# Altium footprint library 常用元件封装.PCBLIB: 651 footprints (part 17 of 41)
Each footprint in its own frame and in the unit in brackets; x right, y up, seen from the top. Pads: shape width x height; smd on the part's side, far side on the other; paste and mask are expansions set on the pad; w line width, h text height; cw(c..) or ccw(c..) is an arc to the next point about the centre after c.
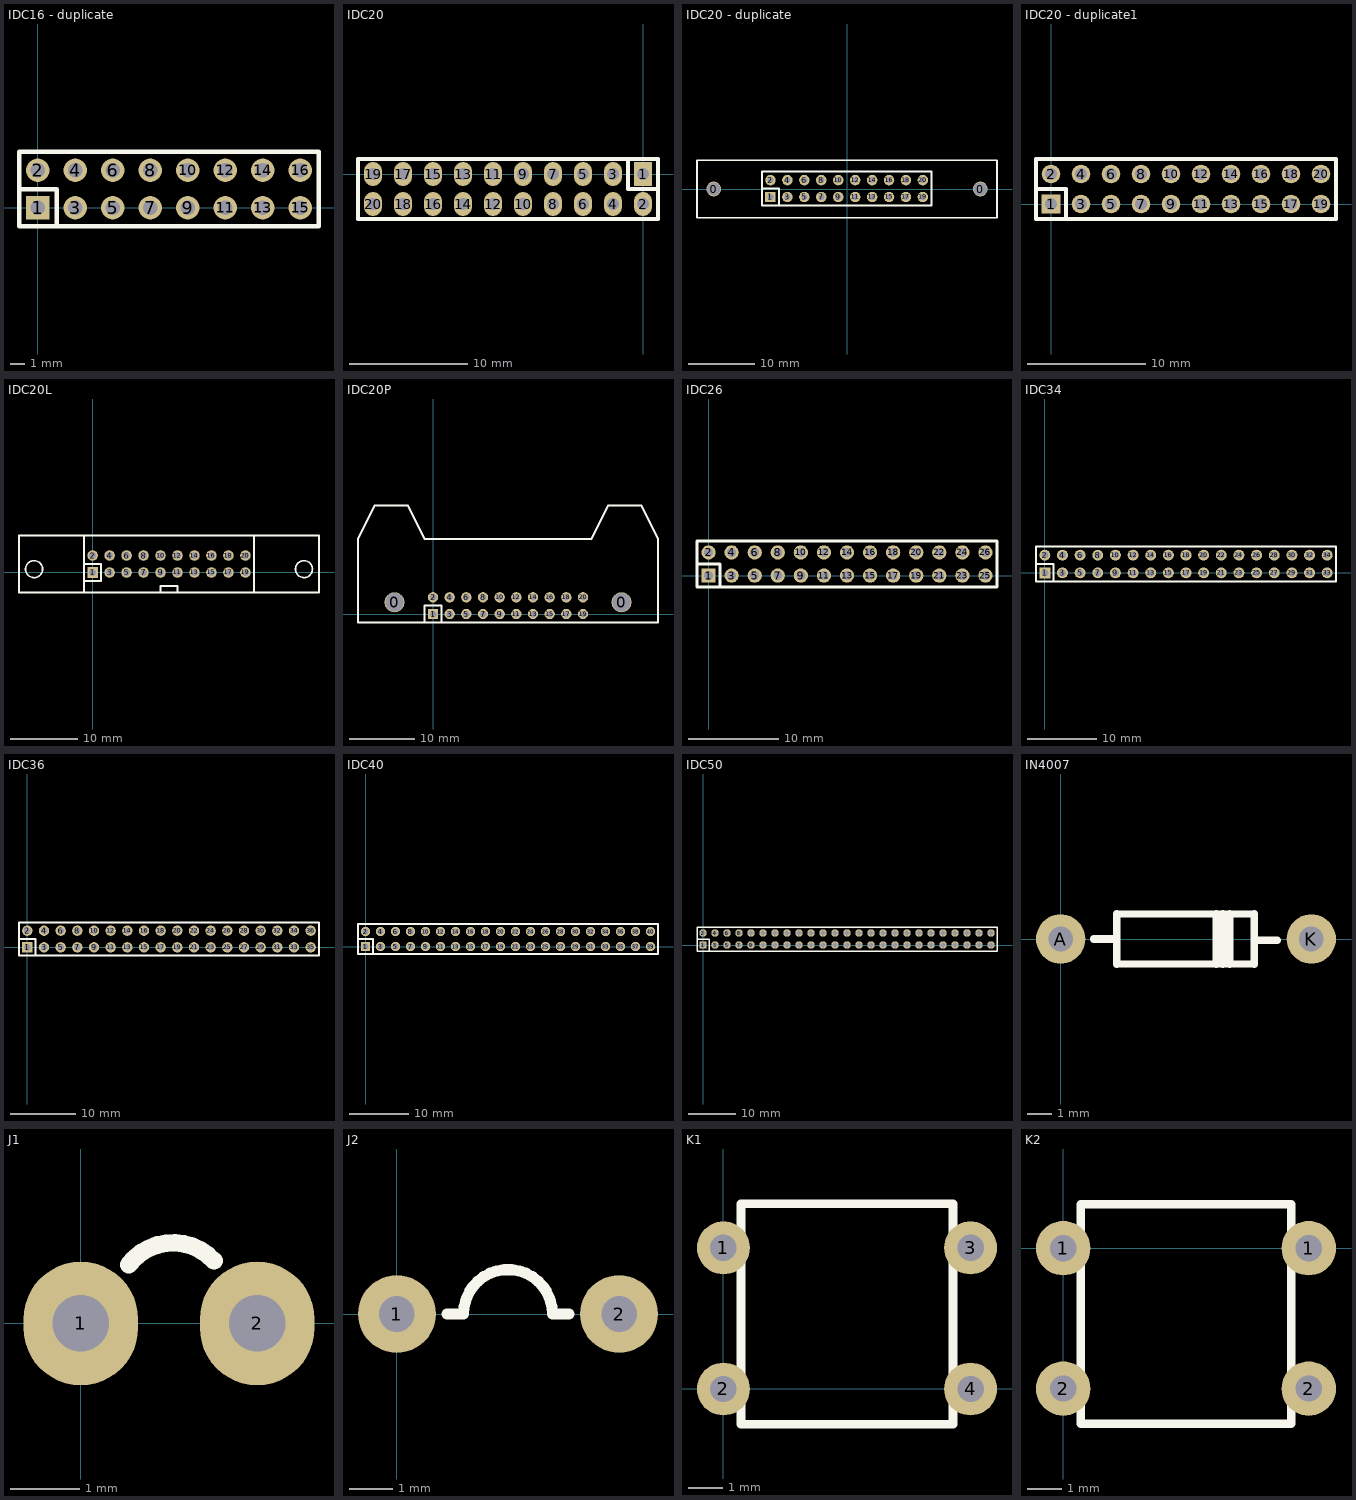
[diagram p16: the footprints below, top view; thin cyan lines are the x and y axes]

## IDC16 - duplicate [mil]
pads (16):
  rect 62x62 hole 39: 1(0,0)
  round 62 hole 39: 2(0,100) 3(100,0) 4(100,100) 5(200,0) 6(200,100) 7(300,0) 8(300,100) 9(400,0) 10(400,100) 11(500,0) 12(500,100) 13(600,0) 14(600,100) 15(700,0) 16(700,100)
TopOverlay:
  lines w12: -50,50 50,50 50,-50 ; -50,-50 750,-50 750,150 -50,150 -50,-50

## IDC20 [mil]
pads (20):
  rect 60x80 hole 40: 1(0,0)
  oval 60x80 hole 40: 2(0,-100) 3(-100,0) 4(-100,-100) 5(-200,0) 6(-200,-100) 7(-300,0) 8(-300,-100) 9(-400,0) 10(-400,-100) 11(-500,0) 12(-500,-100) 13(-600,0) 14(-600,-100) 15(-700,0) 16(-700,-100) 17(-800,0) 18(-800,-100) 19(-900,0) 20(-900,-100)
TopOverlay:
  lines w12: -50,50 -50,-50 50,-50 ; -950,-150 -950,50 50,50 50,-150 -950,-150

## IDC20 - duplicate [mm]
pads (22):
  round 2.2 hole 2: 0(-20,0) 0(20,0)
  rect 1.575x1.575 hole 0.9: 1(-11.476,-1.2)
  round 1.575 hole 0.9: 2(-11.476,1.34) 3(-8.936,-1.2) 4(-8.936,1.34) 5(-6.396,-1.2) 6(-6.396,1.34) 7(-3.856,-1.2) 8(-3.856,1.34) 9(-1.316,-1.2) 10(-1.316,1.34) 11(1.224,-1.2) 12(1.224,1.34) 13(3.764,-1.2) 14(3.764,1.34) 15(6.304,-1.2) 16(6.304,1.34) 17(8.844,-1.2) 18(8.844,1.34) 19(11.384,-1.2) 20(11.384,1.34)
TopOverlay:
  lines w0.254: -22.5,-4.3 -22.5,4.3 22.5,4.3 22.5,-4.3 -22.5,-4.3
  lines w0.305: -12.746,0.07 -10.206,0.07 -10.206,-2.47 ; -12.746,-2.47 12.654,-2.47 12.654,2.61 -12.746,2.61 -12.746,-2.47

## IDC20 - duplicate1 [mil]
pads (20):
  rect 62x62 hole 39: 1(0,0)
  round 62 hole 39: 2(0,100) 3(100,0) 4(100,100) 5(200,0) 6(200,100) 7(300,0) 8(300,100) 9(400,0) 10(400,100) 11(500,0) 12(500,100) 13(600,0) 14(600,100) 15(700,0) 16(700,100) 17(800,0) 18(800,100) 19(900,0) 20(900,100)
TopOverlay:
  lines w12: -50,50 50,50 50,-50 ; -50,-50 950,-50 950,150 -50,150 -50,-50

## IDC20L [mil]
pads (20):
  rect 62x62 hole 39: 1(0,0)
  round 62 hole 39: 2(0,100) 3(100,0) 4(100,100) 5(200,0) 6(200,100) 7(300,0) 8(300,100) 9(400,0) 10(400,100) 11(500,0) 12(500,100) 13(600,0) 14(600,100) 15(700,0) 16(700,100) 17(800,0) 18(800,100) 19(900,0) 20(900,100)
TopOverlay:
  circle w10: c1244.49,19.68 r50
  circle w10: c-344.49,19.68 r50
  lines w12: -50,-118.11 -50,218.11 ; -50,-50 50,-50 50,50 -50,50 ; 400,-118.11 400,-80 500,-80 500,-118.11 ; 950,-118.11 950,218.11 ; -433.07,-118.11 -433.07,218.11 1333.07,218.11 1333.07,-118.11 -433.07,-118.11

## IDC20P [mil]
pads (22):
  round 120 hole 110: 0(-231,70) 0(1131,70)
  rect 62x62 hole 39: 1(0,0)
  round 62 hole 39: 2(0,100) 3(100,0) 4(100,100) 5(200,0) 6(200,100) 7(300,0) 8(300,100) 9(400,0) 10(400,100) 11(500,0) 12(500,100) 13(600,0) 14(600,100) 15(700,0) 16(700,100) 17(800,0) 18(800,100) 19(900,0) 20(900,100)
TopOverlay:
  lines w12: -50,-50 -50,50 50,50 50,-50 ; -450,-50 -450,450 -350,650 -150,650 -50,450 950,450 1050,650 1250,650 1350,450 1350,-50 -450,-50

## IDC26 [mil]
pads (26):
  rect 62x62 hole 39: 1(0,0)
  round 62 hole 39: 2(0,100) 3(100,0) 4(100,100) 5(200,0) 6(200,100) 7(300,0) 8(300,100) 9(400,0) 10(400,100) 11(500,0) 12(500,100) 13(600,0) 14(600,100) 15(700,0) 16(700,100) 17(800,0) 18(800,100) 19(900,0) 20(900,100) 21(1000,0) 22(1000,100) 23(1100,0) 24(1100,100) 25(1200,0) 26(1200,100)
TopOverlay:
  lines w12: -50,50 50,50 50,-50 ; -50,-50 1250,-50 1250,150 -50,150 -50,-50

## IDC34 [mil]
pads (34):
  rect 62x62 hole 39: 1(0,0)
  round 62 hole 39: 2(0,100) 3(100,0) 4(100,100) 5(200,0) 6(200,100) 7(300,0) 8(300,100) 9(400,0) 10(400,100) 11(500,0) 12(500,100) 13(600,0) 14(600,100) 15(700,0) 16(700,100) 17(800,0) 18(800,100) 19(900,0) 20(900,100) 21(1000,0) 22(1000,100) 23(1100,0) 24(1100,100) 25(1200,0) 26(1200,100) 27(1300,0) 28(1300,100) 29(1400,0) 30(1400,100) 31(1500,0) 32(1500,100) 33(1600,0) 34(1600,100)
TopOverlay:
  lines w12: -50,50 50,50 50,-50 ; -50,-50 -50,150 1650,150 1650,-50 -50,-50

## IDC36 [mil]
pads (36):
  rect 62x62 hole 39: 1(0,0)
  round 62 hole 39: 2(0,100) 3(100,0) 4(100,100) 5(200,0) 6(200,100) 7(300,0) 8(300,100) 9(400,0) 10(400,100) 11(500,0) 12(500,100) 13(600,0) 14(600,100) 15(700,0) 16(700,100) 17(800,0) 18(800,100) 19(900,0) 20(900,100) 21(1000,0) 22(1000,100) 23(1100,0) 24(1100,100) 25(1200,0) 26(1200,100) 27(1300,0) 28(1300,100) 29(1400,0) 30(1400,100) 31(1500,0) 32(1500,100) 33(1600,0) 34(1600,100) 35(1700,0) 36(1700,100)
TopOverlay:
  lines w12: -50,50 50,50 50,-50 ; -50,-50 1750,-50 1750,150 -50,150 -50,-50

## IDC40 [mil]
pads (40):
  rect 62x62 hole 39: 1(0,0)
  round 62 hole 39: 2(0,100) 3(100,0) 4(100,100) 5(200,0) 6(200,100) 7(300,0) 8(300,100) 9(400,0) 10(400,100) 11(500,0) 12(500,100) 13(600,0) 14(600,100) 15(700,0) 16(700,100) 17(800,0) 18(800,100) 19(900,0) 20(900,100) 21(1000,0) 22(1000,100) 23(1100,0) 24(1100,100) 25(1200,0) 26(1200,100) 27(1300,0) 28(1300,100) 29(1400,0) 30(1400,100) 31(1500,0) 32(1500,100) 33(1600,0) 34(1600,100) 35(1700,0) 36(1700,100) 37(1800,0) 38(1800,100) 39(1900,0) 40(1900,100)
TopOverlay:
  lines w12: -50,50 50,50 50,-50 ; -50,-50 -50,150 1950,150 1950,-50 -50,-50

## IDC50 [mil]
pads (50):
  rect 62x62 hole 39: 1(0,0)
  round 62 hole 39: 2(0,100) 3(100,0) 4(100,100) 5(200,0) 6(200,100) 7(300,0) 8(300,100) 9(400,0) 10(400,100) 11(500,0) 12(500,100) 13(600,0) 14(600,100) 15(700,0) 16(700,100) 17(800,0) 18(800,100) 19(900,0) 20(900,100) 21(1000,0) 22(1000,100) 23(1100,0) 24(1100,100) 25(1200,0) 26(1200,100) 27(1300,0) 28(1300,100) 29(1400,0) 30(1400,100) 31(1500,0) 32(1500,100) 33(1600,0) 34(1600,100) 35(1700,0) 36(1700,100) 37(1800,0) 38(1800,100) 39(1900,0) 40(1900,100) 41(2000,0) 42(2000,100) 43(2100,0) 44(2100,100) 45(2200,0) 46(2200,100) 47(2300,0) 48(2300,100) 49(2400,0) 50(2400,100)
TopOverlay:
  lines w12: -50,50 50,50 50,-50 ; -50,-50 -50,150 2450,150 2450,-50 -50,-50

## IN4007 [mm]
pads (2):
  round 2 hole 1: A(0,0) K(10.16,0)
TopOverlay:
  lines w0.305: 1.35,0 2.282,0 ; 2.282,-1.016 2.282,1.016 ; 2.289,-1.007 7.841,-1.014 ; 2.289,1.007 7.841,1.014 ; 6.3,-1.016 6.3,1.016 ; 6.575,-1.016 6.575,1.016 ; 6.85,-1.016 6.85,1.016 ; 7.853,-1.016 7.853,1.016 ; 7.853,-0.05 8.785,-0.05

## J1 [mil] "2.54mm"
pads (2):
  oval 65x70 hole 32: 1(0,0) 2(100,0)
TopOverlay:
  lines w10: 27.21,33.32 cw(c52.28,14.25) 75.54,35.49

## J2 [mil] "5.08mm"
pads (2):
  round 70 hole 32: 1(0,0) 2(200,0)
TopOverlay:
  lines w10: 45,0 60,0 cw(c100,0) 140,0 155,0

## K1 [mil] "7.112mmX4.064mm外宽6.35mmX6.604mm"
pads (4):
  round 60 hole 30: 1(0,160) 2(0,0) 3(280,160) 4(280,0)
TopOverlay:
  lines w10: 20,-40 20,210 260,210 260,-40 20,-40

## K2 [mil] "7.112mmX4.064mm外宽6.35mmX6.604mm"
pads (4):
  round 62 hole 30: 1(0,0) 1(280,0) 2(0,-160) 2(280,-160)
TopOverlay:
  lines w10: 20,-200 20,50 260,50 260,-200 20,-200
